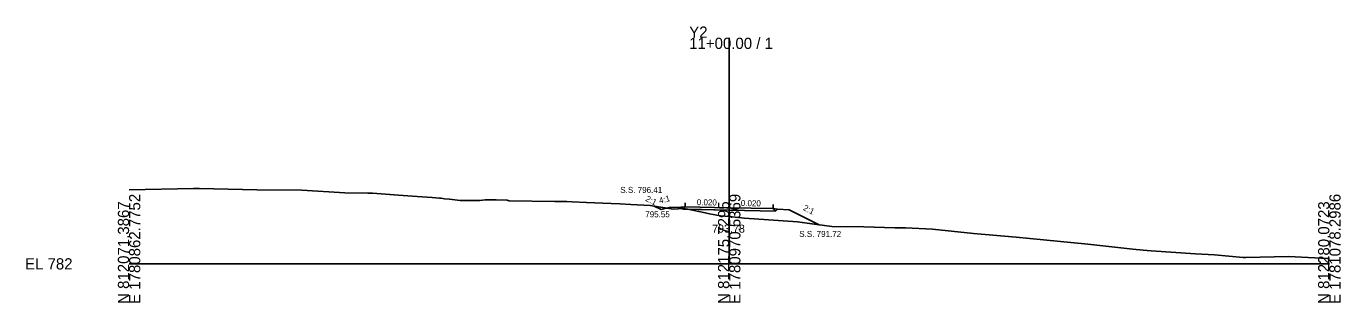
# Model space of a CAD drawing. Extents: x -26 to 303, y -10 to 3096.
# Drawn here: x -25.7 to 302.8, y 1490.3 to 1559.3 of the extents above; entities that cross this region are included whole.
import ezdxf

# ---------------------------------------------------------------- set-up
doc = ezdxf.new("R2010")
doc.units = 0
for name, color, linetype in [('Exist Cross Section Cell', 7, 'Continuous'), ('Exist XS Center Line Elevation Label', 7, 'Continuous'), ('Exist XS Ground Line', 7, 'Continuous'), ('Prop XS Ditch Slope Text', 7, 'Continuous'), ('Prop XS Ditch Standard Text', 7, 'Continuous'), ('Prop XS Dump Level', 7, 'Continuous'), ('Prop XS Earthwork Shape', 7, 'Continuous'), ('Prop XS EOT Tick Mark', 7, 'Continuous'), ('Prop XS Finish Grade', 7, 'Continuous'), ('Prop XS Finish Grade Earthwork', 7, 'Continuous'), ('Prop XS Finish Grade Pavement', 7, 'Continuous'), ('Prop XS Pvmt Edge Slope', 7, 'Continuous'), ('Prop XS SE Text', 7, 'Continuous'), ('Prop XS Side Slope Text', 7, 'Continuous'), ('Prop XS SS Elevation Text', 7, 'Continuous'), ('Prop XS Subgrade Earthwork', 7, 'Continuous')]:
    doc.layers.add(name, color=color, linetype=linetype)

msp = doc.modelspace()

# ---------------------------------------------------------------- linework, layer by layer
at = {"layer": 'Exist Cross Section Cell'}
for p, q in [((150, 1500), (150, 1556.45)), ((0, 1500), (150, 1500)), ((150, 1500), (300, 1500))]:
    msp.add_line(p, q, dxfattribs=at)
at = {"layer": 'Exist XS Ground Line'}
for p, q in [((0, 1518.51), (16.12, 1518.8)), ((16.12, 1518.8), (17.05, 1518.8)), ((17.05, 1518.8), (17.63, 1518.82)), ((17.63, 1518.82), (31.97, 1518.46)), ((31.97, 1518.46), (43.17, 1518.43)), ((43.17, 1518.43), (53.95, 1517.7)), ((53.95, 1517.7), (59.68, 1517.61)), ((59.68, 1517.61), (60.88, 1517.61)), ((60.88, 1517.61), (67.38, 1517.16)), ((67.38, 1517.16), (72.02, 1516.81)), ((72.02, 1516.81), (73.24, 1516.7)), ((73.24, 1516.7), (75.77, 1516.58)), ((75.77, 1516.58), (77.62, 1516.42)), ((77.62, 1516.42), (77.97, 1516.37)), ((77.97, 1516.37), (78.84, 1516.27)), ((78.84, 1516.27), (80.06, 1516.18)), ((80.06, 1516.18), (82.74, 1515.82)), ((82.74, 1515.82), (84.25, 1515.78)), ((84.25, 1515.78), (87.64, 1515.83)), ((87.64, 1515.83), (88.98, 1515.95)), ((88.98, 1515.95), (91.77, 1515.96)), ((91.77, 1515.96), (94.52, 1515.9)), ((94.52, 1515.9), (94.97, 1515.74)), ((94.97, 1515.74), (106.38, 1515.59)), ((106.38, 1515.59), (109.41, 1515.55)), ((109.41, 1515.55), (110.73, 1515.49)), ((110.73, 1515.49), (114.33, 1515.34)), ((114.33, 1515.34), (120.5, 1515.07)), ((120.5, 1515.07), (122.63, 1514.99)), ((122.63, 1514.99), (125.45, 1514.82)), ((125.45, 1514.82), (130.24, 1514.57)), ((130.24, 1514.57), (136.07, 1513.61)), ((136.07, 1513.61), (138.37, 1513.8)), ((138.37, 1513.8), (139.02, 1513.74)), ((139.02, 1513.74), (139.64, 1513.61)), ((139.64, 1513.61), (144.03, 1512.72)), ((144.03, 1512.72), (145.08, 1512.52)), ((145.08, 1512.52), (147.86, 1512.01)), ((147.86, 1512.01), (150, 1511.78)), ((150, 1511.78), (153.81, 1511.38)), ((153.81, 1511.38), (167.03, 1510.48)), ((167.03, 1510.48), (175.64, 1509.29)), ((175.64, 1509.29), (183.61, 1509.21)), ((183.61, 1509.21), (191.43, 1508.99)), ((191.43, 1508.99), (194.05, 1508.97)), ((194.05, 1508.97), (200.85, 1508.63)), ((200.85, 1508.63), (211.04, 1507.57)), ((211.04, 1507.57), (221.71, 1506.67)), ((221.71, 1506.67), (228.55, 1506.03)), ((228.55, 1506.03), (239.67, 1504.92)), ((239.67, 1504.92), (250.89, 1503.69)), ((250.89, 1503.69), (253.45, 1503.45)), ((253.45, 1503.45), (255.48, 1503.26)), ((255.48, 1503.26), (266.51, 1502.51)), ((266.51, 1502.51), (271.33, 1502.21)), ((271.33, 1502.21), (278.43, 1501.58)), ((278.43, 1501.58), (279.15, 1501.59)), ((279.15, 1501.59), (289.77, 1501.81)), ((289.77, 1501.81), (296.36, 1501.5)), ((296.36, 1501.5), (297.83, 1501.43)), ((297.83, 1501.43), (299.42, 1501.35)), ((299.42, 1501.35), (300, 1501.33))]:
    msp.add_line(p, q, dxfattribs=at)
at = {"layer": 'Prop XS Dump Level'}
for p, q in [((139, 1514.22), (150, 1514)), ((150, 1514), (161, 1513.78))]:
    msp.add_line(p, q, dxfattribs=at)
at = {"layer": 'Prop XS Earthwork Shape'}
for points in [[(132.96, 1513.55), (131.25, 1514.41), (134.34, 1513.9)], [(138.28, 1513.8), (137.9, 1514.18), (135, 1514.06), (134.34, 1513.9), (136.07, 1513.61)], [(138.28, 1513.8), (138.37, 1513.8), (139.02, 1513.74), (139.55, 1513.63), (138.43, 1513.65)], [(139.55, 1513.63), (139.64, 1513.61), (144.03, 1512.72), (145.08, 1512.52), (147.86, 1512.01), (150, 1511.78), (153.81, 1511.38), (167.03, 1510.48), (172.48, 1509.72), (165, 1513.46), (162.1, 1513.69), (161.6, 1513.19), (149.99, 1513.42)]]:
    msp.add_lwpolyline(points, close=True, dxfattribs=at)
at = {"layer": 'Prop XS EOT Tick Mark'}
for p, q in [((139, 1514.22), (139, 1515.22)), ((161, 1513.78), (161, 1514.78))]:
    msp.add_line(p, q, dxfattribs=at)
at = {"layer": 'Prop XS Finish Grade'}
for p, q in [((139, 1514.22), (137.9, 1514.18)), ((161, 1513.78), (162.1, 1513.69))]:
    msp.add_line(p, q, dxfattribs=at)
at = {"layer": 'Prop XS Finish Grade Earthwork'}
for p, q in [((132.96, 1513.55), (131.25, 1514.41)), ((135, 1514.06), (132.96, 1513.55)), ((137.9, 1514.18), (135, 1514.06)), ((162.1, 1513.69), (165, 1513.46)), ((165, 1513.46), (172.48, 1509.72))]:
    msp.add_line(p, q, dxfattribs=at)
at = {"layer": 'Prop XS Finish Grade Pavement'}
for p, q in [((139, 1514.22), (150, 1514)), ((150, 1514), (161, 1513.78))]:
    msp.add_line(p, q, dxfattribs=at)
at = {"layer": 'Prop XS Pvmt Edge Slope'}
for p, q in [((139, 1514.22), (138.43, 1513.65)), ((161, 1513.78), (161.6, 1513.19))]:
    msp.add_line(p, q, dxfattribs=at)
at = {"layer": 'Prop XS Subgrade Earthwork'}
for p, q in [((138.43, 1513.65), (137.9, 1514.18)), ((138.43, 1513.65), (149.99, 1513.42)), ((149.99, 1513.42), (161.6, 1513.19)), ((161.6, 1513.19), (162.1, 1513.69))]:
    msp.add_line(p, q, dxfattribs=at)

# ---------------------------------------------------------------- texts
at = {"layer": 'Exist Cross Section Cell'}
for s, p in [('Y2', (140, 1556.45)), ('11+00.00 / 1', (140, 1553.65)), ('EL 782', (-26, 1498.6))]:
    msp.add_text(s, height=2.8, dxfattribs=at).set_placement(p)
for s, p in [('N 812071.3867', (0, 1490)), ('E 1780862.7752', (2.8, 1490)), ('N 812175.7295', (150, 1490)), ('E 1780970.5369', (152.8, 1490)), ('N 812280.0723', (300, 1490)), ('E 1781078.2986', (302.8, 1490))]:
    msp.add_text(s, height=2.8, rotation=90, dxfattribs=at).set_placement(p)
at = {"layer": 'Exist XS Center Line Elevation Label'}
msp.add_text('793.78', height=2, dxfattribs=at).set_placement((145.73, 1507.78))
at = {"layer": 'Prop XS Ditch Slope Text'}
msp.add_text('4:1', height=1.5, rotation=14.0362, dxfattribs=at).set_placement((132.64, 1515.02))
at = {"layer": 'Prop XS Ditch Standard Text'}
msp.add_text('795.55', height=1.5, dxfattribs=at).set_placement((129.01, 1511.62))
at = {"layer": 'Prop XS Dump Level'}
for p in [(135, 1514.02), (165, 1513.42)]:
    msp.add_text('Case1', height=0.04, dxfattribs=at).set_placement(p)
at = {"layer": 'Prop XS SE Text'}
for p in [(141.88, 1514.66), (152.88, 1514.44)]:
    msp.add_text('0.020', height=1.5, rotation=358.8542, dxfattribs=at).set_placement(p)
at = {"layer": 'Prop XS Side Slope Text'}
for p in [(128.94, 1515.77), (168.33, 1513.48)]:
    msp.add_text('2:1', height=1.5, rotation=333.4349, dxfattribs=at).set_placement(p)
at = {"layer": 'Prop XS SS Elevation Text'}
for s, p in [('S.S. 796.41', (122.78, 1517.71)), ('S.S. 791.72', (167.51, 1506.72))]:
    msp.add_text(s, height=1.5, dxfattribs=at).set_placement(p)

doc.saveas('drawing.dxf')
